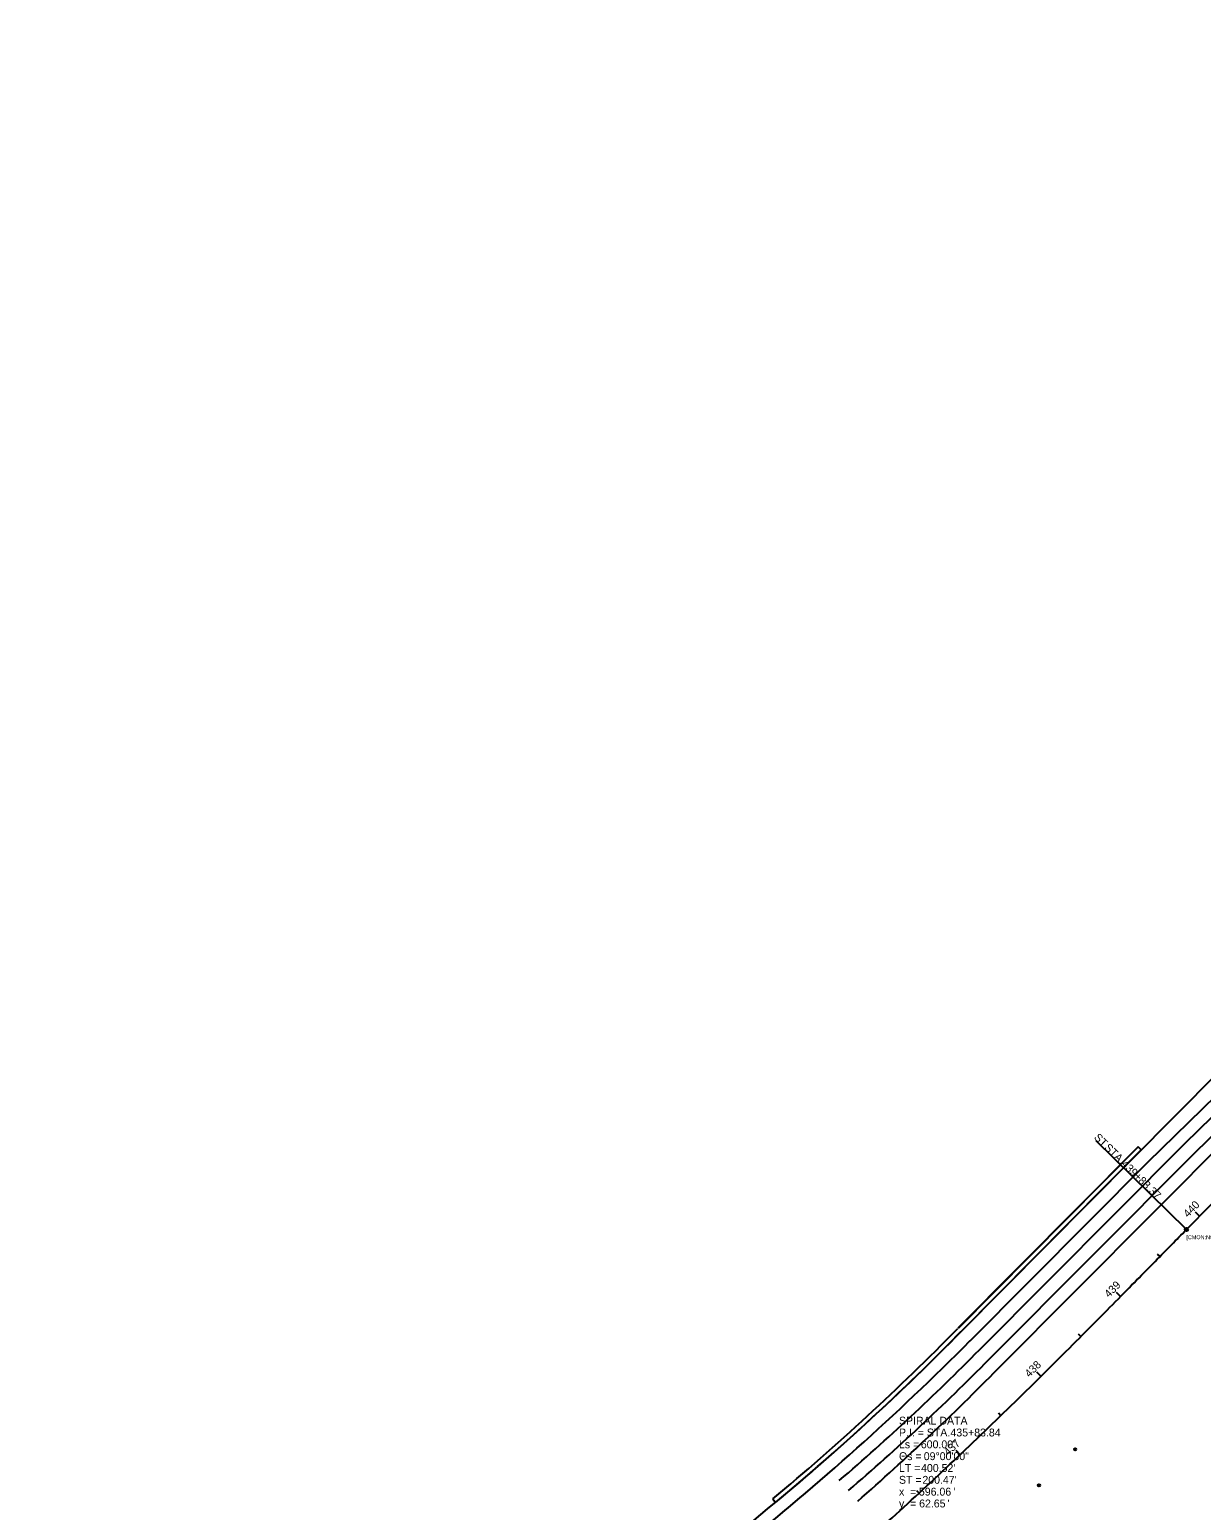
# Model space of a CAD drawing. Extents: x 142554 to 147512, y 370190 to 373751.
# Drawn here: x 143349 to 144390, y 370854 to 372168 of the extents above; entities that cross this region are included whole.
import ezdxf

# ---------------------------------------------------------------- set-up
doc = ezdxf.new("R2010")
doc.units = 0
for name, color, linetype in [('DR_P_Cells', 7, 'Continuous'), ('DR_X_GenericNode', 7, 'Continuous'), ('FeatureService_Stream Network', 7, 'Continuous'), ('FeatureService_Water Bodies', 7, 'Continuous'), ('PM_X_Channelizing_Line', 7, 'Continuous'), ('PM_X_Edge_Line', 7, 'Continuous'), ('PM_X_Transverse_Line', 7, 'Continuous'), ('PV_X_Shoulder', 7, 'Continuous'), ('RD_X_GR_Cable_Bar', 7, 'Continuous'), ('SC_Scratch20', 7, 'Continuous')]:
    doc.layers.add(name, color=color, linetype=linetype)

msp = doc.modelspace()

# ---------------------------------------------------------------- linework, layer by layer
at = {"layer": 'DR_P_Cells'}
for p, q in [((144192.6, 370996.2), (144375.1, 371179.5)), ((144201.1, 370987.7), (144383.6, 371170.9))]:
    msp.add_line(p, q, dxfattribs=at)
for points in [[(144375.1, 371179.5), (144652.7, 371450.3), (144919, 371721.5), (144932, 371734.8), (145131.6, 371942.9), (145332.9, 372147.7)], [(144383.6, 371170.9), (144661.2, 371441.8), (144927.6, 371713.2), (144940.6, 371726.5), (145140.2, 371934.5), (145341.5, 372139.3)]]:
    msp.add_lwpolyline(points, dxfattribs=at)
for centre, radius, start in [((142701.8, 372469.4), 2095.9, 310.6849), ((142702.5, 372468.8), 2107, 310.6921)]:
    msp.add_arc(centre, radius, start, 315.3391, dxfattribs=at)
at = {"layer": 'DR_X_GenericNode'}
for p, q in [((144209.2, 370979.6), (144416.1, 371187.3)), ((144184.3, 371004.2), (144342.4, 371162.9))]:
    msp.add_line(p, q, dxfattribs=at)
msp.add_lwpolyline([(144342.4, 371162.9), (144644.8, 371458), (144911.1, 371729.1), (144924, 371742.3), (145123.6, 371950.4), (145325, 372155.3)], dxfattribs=at)
for centre, radius, start, end in [((142449.8, 372731.5), 2447.9, 308.6247, 315.1207), ((142571.5, 372589.5), 2296.5, 311.2118, 315.4893)]:
    msp.add_arc(centre, radius, start, end, dxfattribs=at)
at = {"layer": 'FeatureService_Stream Network'}
for centre in [(144277.5, 370907.8), (144245.3, 370875.9)]:
    msp.add_circle(centre, 1, dxfattribs=at)
at = {"layer": 'FeatureService_Water Bodies'}
for p, q in [((144333.3, 371176.3), (144173.4, 371015.2)), ((144333.4, 371176.3), (144173.5, 371015.1)), ((144336.2, 371173.5), (144333.4, 371176.3)), ((144336.2, 371173.5), (144333.4, 371176.2)), ((144176.3, 371012.4), (144336.2, 371173.5)), ((144176.3, 371012.3), (144336.2, 371173.5)), ((144009, 370863.8), (144011.6, 370860.7)), ((144009.1, 370863.7), (144011.6, 370860.6))]:
    msp.add_line(p, q, dxfattribs=at)
for radius in [2246, 2246, 2250, 2250]:
    msp.add_arc((142571.7, 372589.6), radius, 309.7888, 315.4923, dxfattribs=at)
at = {"layer": 'PM_X_Channelizing_Line'}
msp.add_line((144376.2, 371102.8), (144296, 371181.6), dxfattribs=at)
msp.add_circle((144376.2, 371102.8), 1.5, dxfattribs=at)
at = {"layer": 'PM_X_Edge_Line'}
msp.add_line((144376.2, 371102.8), (145360.6, 372105.1), dxfattribs=at)
msp.add_open_spline([(143934.5, 370697.8), (143944.5, 370705.2), (143964.5, 370720.3), (144003.8, 370751.2), (144052, 370791), (144108.3, 370840.5), (144163.4, 370891.4), (144217.5, 370943.3), (144270.9, 370996.1), (144314.9, 371040.4), (144350, 371076.1), (144367.5, 371093.9), (144376.2, 371102.8)], degree=3, dxfattribs=at)
at = {"layer": 'RD_X_GR_Cable_Bar'}
for p, q in [((144387.9, 371114.7), (144384.3, 371118.2)), ((144352.8, 371079), (144350.7, 371081.1)), ((144317.8, 371043.4), (144314.2, 371046.9)), ((144282.5, 371007.9), (144280.4, 371010)), ((144247.1, 370972.6), (144243.6, 370976.2)), ((144211.4, 370937.6), (144209.3, 370939.8)), ((144175.3, 370903), (144171.9, 370906.6)), ((144138.9, 370868.8), (144136.8, 370871))]:
    msp.add_line(p, q, dxfattribs=at)
at = {"layer": 'SC_Scratch20'}
msp.add_lwpolyline([(144176.1, 371012.2), (144557, 371396.1), (144910.5, 371756), (145111.7, 371964), (145312.1, 372167.9)], dxfattribs=at)
msp.add_arc((142571.5, 372589.5), 2250, 290.2255, 315.4923, dxfattribs=at)

# ---------------------------------------------------------------- texts
at = {"layer": 'PM_X_Channelizing_Line'}
for s, p in [('ST', (144293.7, 371184)), (' STA. ', (144301, 371176.8)), ('439+83.37', (144317.9, 371160.3))]:
    msp.add_text(s, height=7, rotation=315.5169, dxfattribs=at).set_placement(p)
at = {"layer": 'PM_X_Transverse_Line'}
for s, p in [('SPIRAL DATA', (144121.1, 370929.7)), ('P.I. = STA. ', (144121.1, 370919.2)), ('435+83.84', (144166.8, 370919.2)), ('Ls = ', (144121.1, 370908.7)), ("600.00'", (144140.5, 370908.7)), ('Θs = ', (144121.1, 370898.2)), ('09°00\'00"', (144143.1, 370898.2)), ('LT = ', (144121.1, 370887.7)), ("400.52'", (144140.7, 370887.7)), ('ST = ', (144121.1, 370877.2)), ('596.06', (144138.8, 370866.7)), ("200.47'", (144141.9, 370877.2)), ("'", (144169.6, 370866.7)), ('y  = ', (144121.1, 370856.2)), ('x  = ', (144121.1, 370866.7)), ('62.65', (144139, 370856.2)), ("'", (144164.1, 370856.2))]:
    msp.add_text(s, height=7, dxfattribs=at).set_placement(p)
at = {"layer": 'PV_X_Shoulder'}
msp.add_text('[CMON:NOTE]:CENTERLINE MON', height=3.5, dxfattribs=at).set_placement((144376.2, 371094.3))
at = {"layer": 'RD_X_GR_Cable_Bar'}
for s, rotation, p in [('440', 45.5169, (144377.6, 371113.1)), ('439', 45.3431, (144307.5, 371041.9)), ('438', 44.6763, (144236.8, 370971.2)), ('437', 43.5094, (144164.8, 370901.6))]:
    msp.add_text(s, height=7, rotation=rotation, dxfattribs=at).set_placement(p)

doc.saveas('drawing.dxf')
